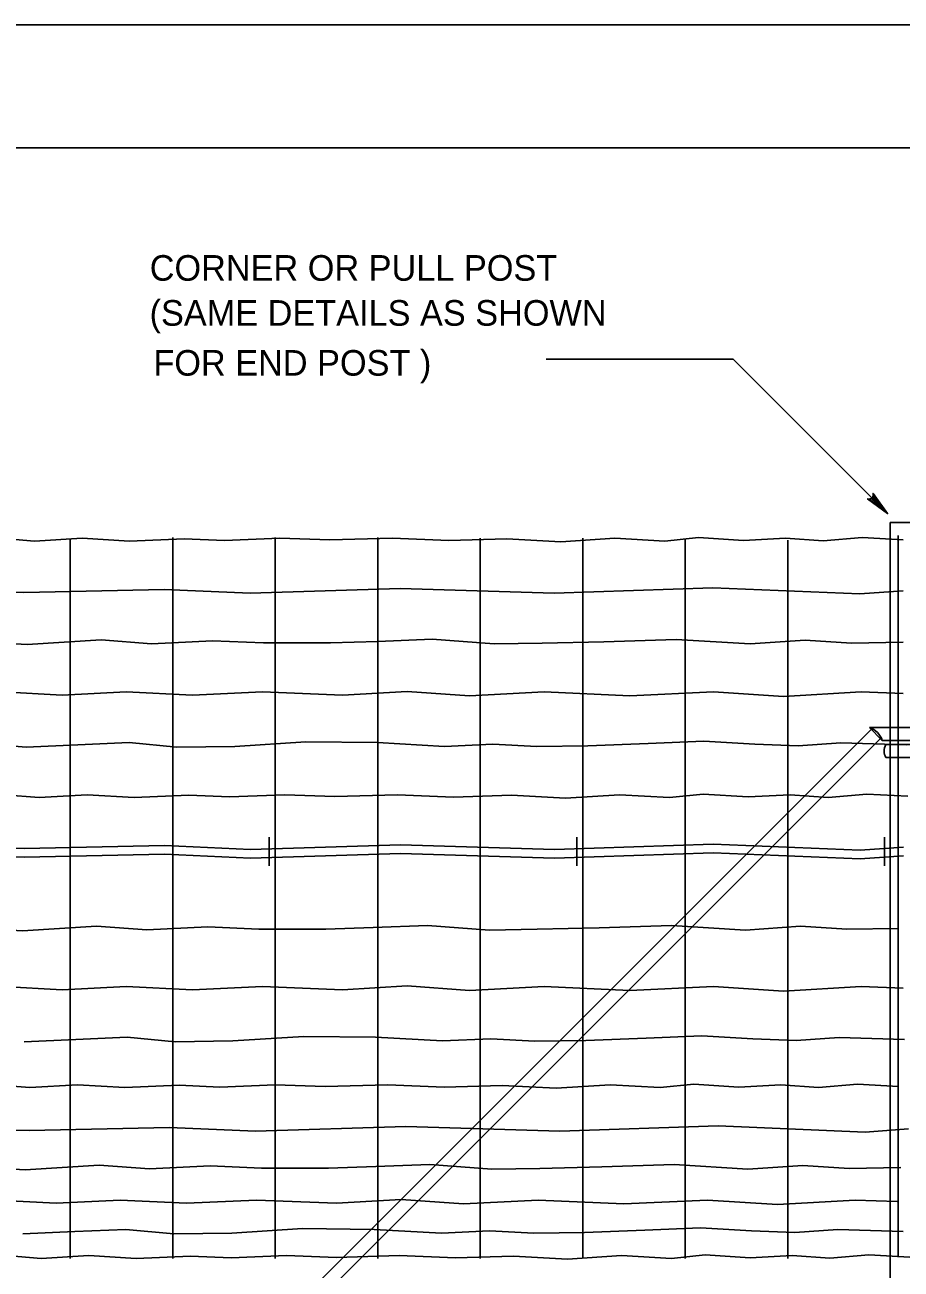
# Model space of a CAD drawing. Extents: x 13 to 918, y -903 to 879.
# Drawn here: x 445.7 to 552.5, y 727.2 to 878.9 of the extents above; entities that cross this region are included whole.
import ezdxf

# ---------------------------------------------------------------- set-up
doc = ezdxf.new("R2010")
doc.units = 0
for name, color, linetype in [('1', 7, 'Continuous'), ('2', 7, 'Continuous'), ('3', 7, 'Continuous'), ('PLT-BNDY', 7, 'Continuous')]:
    doc.layers.add(name, color=color, linetype=linetype)

msp = doc.modelspace()

# ---------------------------------------------------------------- linework, layer by layer
at = {"layer": '1'}
msp.add_lwpolyline([(839.2505, 299.93025), (839.2505, 863.93025), (53.2505, 863.93025), (53.2505, 299.93025), (839.2505, 299.93025), (839.2505, 326.28925), (639.2505, 326.28925), (639.2505, 390.96675), (839.2505, 390.96675), (839.2505, 419.93025), (639.2505, 419.93025), (639.2505, 299.93025), (718.052, 299.93025), (718.052, 326.28925), (718.052, 299.93025), (795.052, 299.93025), (795.052, 326.28925), (795.052, 313.97275), (839.2505, 313.97275)], dxfattribs=at)
at = {"layer": '2'}
for p, q in [((509.24425, 838.1765), (532.04175, 838.1765)), ((550.89175, 819.3265), (532.04175, 838.1765)), ((551.2105, 818.2225), (551.2105, 692.17025)), ((551.2105, 818.2225), (554.3355, 818.2225)), ((552.16875, 816.64125), (552.16875, 728.64325)), ((451.2105, 816.18075), (451.2105, 728.47025)), ((463.7105, 816.41), (463.7105, 728.47025)), ((476.2105, 816.41), (476.2105, 728.47025)), ((488.7105, 816.41), (488.7105, 728.47025)), ((501.2105, 816.314), (501.2105, 728.47025)), ((513.7105, 816.314), (513.7105, 728.47025)), ((526.2105, 816.1995), (526.2105, 728.47025)), ((538.7105, 816.085), (538.7105, 728.47025)), ((548.898, 792.99525), (472.43125, 716.52875)), ((548.671, 793.2225), (554.93975, 793.2225)), ((548.671, 793.2225), (550.2335, 791.66)), ((549.42725, 792.46625), (549.42725, 792.46625)), ((550.00625, 791.887), (473.53975, 715.42025)), ((550.2335, 791.66), (554.93975, 791.66)), ((550.68975, 791.139), (557.0105, 791.139)), ((550.68975, 789.5765), (555.448, 789.5765)), ((475.49375, 779.87025), (475.49375, 776.34125)), ((512.99375, 779.87025), (512.99375, 776.34125)), ((550.49375, 779.87025), (550.49375, 776.34125)), ((513.56675, 756.50375), (513.56675, 756.50375))]:
    msp.add_line(p, q, dxfattribs=at)
for points in [[(442.59175, 816.314), (446.85, 815.97025), (452.68125, 816.314), (458.4355, 815.97025), (465.09175, 816.25775), (470.03975, 816.04525), (476.79175, 816.314), (482.89175, 816.10375), (490.525, 816.314), (497.373, 816.0265), (504.45225, 816.237), (511.03125, 815.89325), (517.6105, 816.314), (523.72925, 815.97025), (527.81475, 816.39125), (533.3, 816.04525), (538.44175, 816.314), (543.046, 815.989), (547.7835, 816.39125), (552.773, 816.12875)], [(402.846, 809.92025), (402.773, 809.889), (408.38975, 809.9765), (413.77925, 810.0725), (419.171, 809.612), (430.2375, 810.0725), (445.56475, 809.70775), (462.675, 810.0725), (473.16675, 809.612), (491.46675, 810.16825), (510.24375, 809.612), (529.5605, 810.264), (547.496, 809.51625), (552.773, 809.889)], [(402.86475, 803.61825), (402.773, 803.639), (408.63975, 803.639), (414.6625, 803.81), (420.148, 803.3495), (427.13125, 803.735), (433.173, 803.44525), (439.196, 803.735), (445.9855, 803.3495), (455.00225, 803.90575), (461.13975, 803.44525), (468.5625, 803.81), (474.796, 803.54125), (482.96875, 803.54125), (488.74175, 803.735), (495.33975, 804.0015), (502.898, 803.4265), (508.748, 803.5225), (516.2875, 803.69525), (525.1105, 803.98275), (534.125, 803.4265), (540.821, 803.887), (546.47925, 803.5225), (552.773, 803.639)], [(402.998, 797.37875), (402.773, 797.389), (407.56475, 797.085), (412.49375, 797.46825), (418.25, 797.564), (423.448, 797.2765), (429.5855, 797.564), (435.91475, 797.18075), (442.975, 797.564), (450.225, 797.18075), (458.03125, 797.564), (466.1085, 797.18075), (474.6625, 797.564), (484.42725, 797.18075), (492.3105, 797.64125), (499.90625, 797.10375), (509.01675, 797.564), (519.4335, 797.10375), (529.65625, 797.564), (538.19175, 797.00775), (547.66875, 797.564), (552.773, 797.37875)], [(439.98975, 791.31625), (445.83975, 790.837), (452.15225, 791.1245), (458.3855, 791.39325), (464.2355, 790.837), (471.29375, 790.93275), (479.946, 791.489), (488.673, 791.39325), (496.86475, 790.93275), (502.7335, 791.2015), (508.123, 790.914), (514.3375, 791.01), (521.6855, 791.27875), (528.475, 791.56625), (534.68975, 791.2015), (539.9835, 791.01), (545.20225, 791.3745), (553.16475, 791.12875)], [(443.173, 785.037), (447.43125, 784.69325), (453.2625, 785.037), (459.01675, 784.69325), (465.673, 784.98075), (470.621, 784.76825), (477.373, 785.037), (483.473, 784.8265), (491.10625, 785.037), (497.95425, 784.7495), (505.0335, 784.96), (511.6125, 784.61625), (518.19175, 785.037), (524.3105, 784.69325), (528.396, 785.114), (533.88125, 784.76825), (539.023, 785.037), (543.62725, 784.712), (548.36475, 785.114), (553.35425, 784.8515)], [(402.773, 778.639), (402.81475, 778.639), (408.43125, 778.7265), (413.821, 778.8225), (419.2125, 778.362), (430.27925, 778.8225), (445.60625, 778.45775), (462.71675, 778.8225), (473.2085, 778.362), (491.5085, 778.91825), (510.2855, 778.362), (529.60225, 779.014), (547.5375, 778.26625), (552.81475, 778.639)], [(402.773, 777.587), (402.81475, 777.587), (408.43125, 777.6745), (413.821, 777.77025), (419.2125, 777.31), (430.27925, 777.77025), (445.60625, 777.40575), (462.71675, 777.77025), (473.2085, 777.31), (491.5085, 777.86625), (510.2855, 777.31), (529.60225, 777.962), (547.5375, 777.214), (552.81475, 777.587)], [(402.26875, 768.73275), (402.26875, 768.73275), (408.06475, 768.73275), (414.0875, 768.90375), (419.573, 768.44325), (426.55625, 768.82875), (432.598, 768.539), (438.621, 768.82875), (445.4105, 768.44325), (454.42725, 768.9995), (460.56475, 768.539), (467.9875, 768.90375), (474.221, 768.635), (482.39375, 768.635), (488.16675, 768.82875), (494.76475, 769.09525), (502.323, 768.52025), (508.173, 768.61625), (515.7125, 768.789), (524.5355, 769.0765), (533.55, 768.52025), (540.246, 768.98075), (545.90425, 768.61625), (552.198, 768.73275)], [(402.57725, 761.44125), (402.773, 761.4515), (407.56475, 761.1475), (412.49375, 761.53075), (418.25, 761.6265), (423.448, 761.339), (429.5855, 761.6265), (435.91475, 761.24325), (442.975, 761.6265), (450.225, 761.24325), (458.03125, 761.6265), (466.1085, 761.24325), (474.6625, 761.6265), (484.42725, 761.24325), (492.3105, 761.70375), (499.90625, 761.16625), (509.01675, 761.6265), (519.4335, 761.16625), (529.65625, 761.6265), (538.19175, 761.07025), (547.66875, 761.6265), (552.773, 761.44125)], [(445.60225, 754.8995), (451.91475, 755.187), (458.148, 755.45575), (463.998, 754.8995), (471.05625, 754.99525), (479.7085, 755.5515), (488.4355, 755.45575), (496.62725, 754.99525), (502.496, 755.264), (507.8855, 754.9765), (514.1, 755.0725), (521.448, 755.34125), (528.2375, 755.62875), (534.45225, 755.264), (539.746, 755.0725), (544.96475, 755.437), (552.92725, 755.19125)], [(442.01675, 749.6475), (446.275, 749.30375), (452.10625, 749.6475), (457.8605, 749.30375), (464.51675, 749.59125), (469.46475, 749.37875), (476.21675, 749.6475), (482.31675, 749.437), (489.95, 749.6475), (496.798, 749.36), (503.87725, 749.57025), (510.45625, 749.2265), (517.0355, 749.6475), (523.15425, 749.30375), (527.23975, 749.7245), (532.725, 749.37875), (537.86675, 749.6475), (542.471, 749.3225), (547.2085, 749.7245), (552.198, 749.462)], [(403.5, 744.29525), (403.42725, 744.264), (409.04375, 744.3515), (414.4335, 744.4475), (419.825, 743.987), (430.89175, 744.4475), (446.21875, 744.08275), (463.32925, 744.4475), (473.821, 743.987), (492.121, 744.54325), (510.898, 743.987), (530.21475, 744.639), (548.15, 743.89125), (553.42725, 744.264)], [(402.598, 739.55575), (402.50625, 739.5765), (408.373, 739.5765), (414.396, 739.7475), (419.88125, 739.287), (426.86475, 739.6725), (432.90625, 739.38275), (438.92925, 739.6725), (445.71875, 739.287), (454.7355, 739.84325), (460.873, 739.38275), (468.296, 739.7475), (474.52925, 739.47875), (482.70225, 739.47875), (488.475, 739.6725), (495.073, 739.939), (502.63125, 739.364), (508.48125, 739.46), (516.021, 739.63275), (524.84375, 739.92025), (533.8585, 739.364), (540.55425, 739.8245), (546.2125, 739.46), (552.50625, 739.5765)], [(402.26875, 735.3995), (402.04375, 735.41), (406.8355, 735.10575), (411.76475, 735.489), (417.521, 735.585), (422.71875, 735.2975), (428.85625, 735.585), (435.1855, 735.2015), (442.246, 735.585), (449.496, 735.2015), (457.30225, 735.585), (465.37925, 735.2015), (473.9335, 735.585), (483.698, 735.2015), (491.58125, 735.662), (499.17725, 735.1245), (508.2875, 735.585), (518.70425, 735.1245), (528.92725, 735.585), (537.4625, 735.02875), (546.93975, 735.585), (552.04375, 735.3995)], [(445.448, 731.462), (451.7605, 731.7495), (457.99375, 732.01825), (463.84375, 731.462), (470.90225, 731.55775), (479.55425, 732.114), (488.28125, 732.01825), (496.473, 731.55775), (502.34175, 731.8265), (507.73125, 731.539), (513.946, 731.635), (521.29375, 731.90375), (528.0835, 732.19125), (534.298, 731.8265), (539.59175, 731.635), (544.8105, 731.9995), (552.773, 731.75375)], [(443.4, 728.814), (447.6585, 728.47025), (453.48975, 728.814), (459.24375, 728.47025), (465.9, 728.75775), (470.848, 728.54525), (477.6, 728.814), (483.7, 728.60375), (491.3335, 728.814), (498.18125, 728.5265), (505.2605, 728.737), (511.83975, 728.39325), (518.41875, 728.814), (524.5375, 728.47025), (528.623, 728.89125), (534.1085, 728.54525), (539.25, 728.814), (543.85425, 728.489), (548.59175, 728.89125), (553.58125, 728.62875)]]:
    msp.add_lwpolyline(points, dxfattribs=at)
for centre, radius, start, end in [((547.93734, 790.92633), 2.41048, 17.7190667, 72.2809306), ((551.95162, 790.35788), 1.48416, 148.2379917, 211.7620056)]:
    msp.add_arc(centre, radius, start, end, dxfattribs=at)
at = {"layer": '3'}
msp.add_lwpolyline([(549.1375, 821.585), (549.06675, 821.36625), (550.89175, 819.3265), (549.1375, 821.585), (549.123, 821.7765), (550.89175, 819.3265), (548.86675, 821.162), (548.65225, 821.089), (550.89175, 819.3265), (548.446, 821.1015), (548.65225, 821.089)], dxfattribs=at)
at = {"layer": 'PLT-BNDY'}
msp.add_lwpolyline([(13.2505, 878.93025), (854.2505, 878.93025), (854.2505, 284.93025), (13.2505, 284.93025)], close=True, dxfattribs=at)

# ---------------------------------------------------------------- texts
at = {"layer": '3'}
for s, p in [('CORNER OR PULL POST', (460.91, 847.72175)), ('(SAME DETAILS AS SHOWN', (460.8925, 842.23625)), ('FOR END POST )', (461.353, 836.14475))]:
    msp.add_text(s, height=3.1249995, dxfattribs=at).set_placement(p)

doc.saveas('drawing.dxf')
